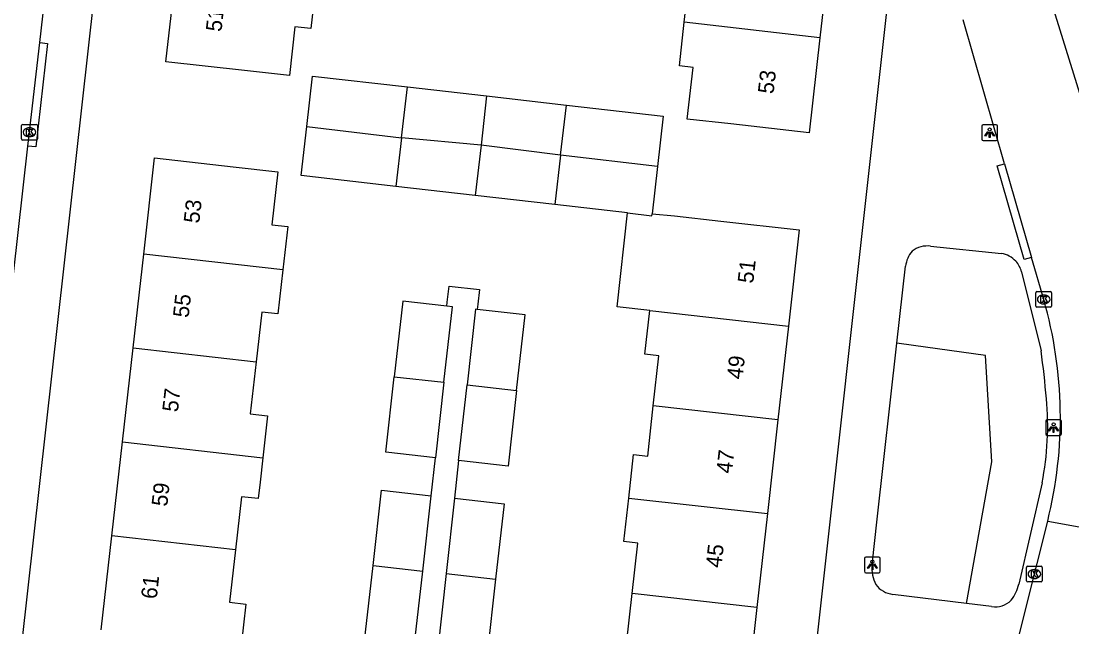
# Model space of a CAD drawing. Extents: x 162026 to 163499, y 387297 to 388169.
# Drawn here: x 162443.5 to 162510, y 387835.8 to 387874.2 of the extents above; entities that cross this region are included whole.
import ezdxf

# ---------------------------------------------------------------- set-up
doc = ezdxf.new("R2010")
doc.units = 0
for name, color, linetype in [('IMGEO_Groenvoorziening', 7, 'Continuous'), ('IMGEO_Kolk', 7, 'Continuous'), ('IMGEO_Lichtpunt', 7, 'Continuous'), ('IMGEO_Pand', 7, 'Continuous'), ('IMGEO_Pand_nummerreeks', 7, 'Continuous'), ('IMGEO_Rijbaan_lokaal_open', 7, 'Continuous'), ('IMGEO_Voetpad_open', 7, 'Continuous')]:
    doc.layers.add(name, color=color, linetype=linetype)

msp = doc.modelspace()

# ---------------------------------------------------------------- linework, layer by layer
at = {"layer": 'IMGEO_Groenvoorziening'}
msp.add_lwpolyline([(162503.359, 387837.251), (162504.95, 387846.219), (162504.552, 387852.97), (162500, 387853.601), (162498.938, 387853.747)], dxfattribs=at)
at = {"layer": 'IMGEO_Kolk'}
for p, q in [((162443.492, 387866.682), (162443.492, 387867.534)), ((162443.567, 387867.608), (162444.419, 387867.608)), ((162443.98, 387867.388), (162444.005, 387867.388)), ((162444.493, 387867.534), (162444.493, 387866.682)), ((162444.419, 387866.608), (162443.567, 387866.608)), ((162444.003, 387866.828), (162443.978, 387866.828)), ((162507.737, 387856.091), (162507.737, 387856.943)), ((162507.812, 387857.017), (162508.664, 387857.017)), ((162508.225, 387856.797), (162508.25, 387856.797)), ((162508.738, 387856.943), (162508.738, 387856.091)), ((162508.664, 387856.017), (162507.812, 387856.017)), ((162508.248, 387856.237), (162508.223, 387856.237)), ((162507.15, 387838.692), (162507.15, 387839.544)), ((162507.225, 387839.618), (162508.077, 387839.618)), ((162507.638, 387839.398), (162507.663, 387839.398)), ((162508.151, 387839.544), (162508.151, 387838.692)), ((162508.077, 387838.618), (162507.225, 387838.618)), ((162507.661, 387838.838), (162507.636, 387838.838))]:
    msp.add_line(p, q, dxfattribs=at)
for points in [[(162443.492, 387866.682), (162443.492, 387867.534)], [(162443.567, 387867.608), (162444.419, 387867.608)], [(162443.813, 387867.308), (162443.936, 387867.308), (162443.936, 387867.157), (162444.066, 387867.308), (162444.23, 387867.308), (162444.084, 387867.157), (162444.237, 387866.908), (162444.085, 387866.908), (162444, 387867.072), (162443.936, 387867.005), (162443.936, 387866.908), (162443.813, 387866.908), (162443.813, 387867.308)], [(162444.493, 387867.534), (162444.493, 387866.682)], [(162444.419, 387866.608), (162443.567, 387866.608)], [(162507.737, 387856.091), (162507.737, 387856.943)], [(162507.812, 387857.017), (162508.664, 387857.017)], [(162508.058, 387856.717), (162508.181, 387856.717), (162508.181, 387856.566), (162508.311, 387856.717), (162508.475, 387856.717), (162508.329, 387856.566), (162508.482, 387856.317), (162508.33, 387856.317), (162508.245, 387856.481), (162508.181, 387856.414), (162508.181, 387856.317), (162508.058, 387856.317), (162508.058, 387856.717)], [(162508.738, 387856.943), (162508.738, 387856.091)], [(162508.664, 387856.017), (162507.812, 387856.017)], [(162507.15, 387838.692), (162507.15, 387839.544)], [(162507.225, 387839.618), (162508.077, 387839.618)], [(162507.471, 387839.318), (162507.594, 387839.318), (162507.594, 387839.167), (162507.724, 387839.318), (162507.888, 387839.318), (162507.742, 387839.167), (162507.895, 387838.918), (162507.743, 387838.918), (162507.658, 387839.082), (162507.594, 387839.015), (162507.594, 387838.918), (162507.471, 387838.918), (162507.471, 387839.318)], [(162508.151, 387839.544), (162508.151, 387838.692)], [(162508.077, 387838.618), (162507.225, 387838.618)]]:
    msp.add_lwpolyline(points, dxfattribs=at)
for centre, start, end in [((162443.569, 387867.532), 91.55205, 178.44795), ((162443.569, 387867.532), 91.55205, 178.44795), ((162444.417, 387867.532), 1.55205, 88.44795), ((162444.417, 387867.532), 1.55205, 88.44795), ((162443.569, 387866.684), 181.55205, 268.44795), ((162443.569, 387866.684), 181.55205, 268.44795), ((162444.417, 387866.684), 271.55205, 358.44795), ((162444.417, 387866.684), 271.55205, 358.44795), ((162507.814, 387856.941), 91.55205, 178.44795), ((162507.814, 387856.941), 91.55205, 178.44795), ((162508.662, 387856.941), 1.55205, 88.44795), ((162508.662, 387856.941), 1.55205, 88.44795), ((162507.814, 387856.093), 181.55205, 268.44795), ((162507.814, 387856.093), 181.55205, 268.44795), ((162508.662, 387856.093), 271.55205, 358.44795), ((162508.662, 387856.093), 271.55205, 358.44795), ((162507.227, 387839.542), 91.55205, 178.44795), ((162507.227, 387839.542), 91.55205, 178.44795), ((162508.075, 387839.542), 1.55205, 88.44795), ((162508.075, 387839.542), 1.55205, 88.44795), ((162507.227, 387838.694), 181.55205, 268.44795), ((162507.227, 387838.694), 181.55205, 268.44795), ((162508.075, 387838.694), 271.55205, 358.44795), ((162508.075, 387838.694), 271.55205, 358.44795)]:
    msp.add_arc(centre, 0.0765, start, end, dxfattribs=at)
for centre, major_axis, ratio, start_param, end_param in [((162443.979, 387867.108), (-0.387, 0.002), 0.722429, 4.712389, 7.853982), ((162444.004, 387867.108), (-0.39, 0.002), 0.717154, 1.570796, 4.712389), ((162508.224, 387856.517), (-0.387, 0.002), 0.722429, 4.712389, 7.853982), ((162508.249, 387856.517), (-0.39, 0.002), 0.717154, 1.570796, 4.712389), ((162507.637, 387839.118), (-0.387, 0.002), 0.722429, 4.712389, 7.853982), ((162507.662, 387839.118), (-0.39, 0.002), 0.717154, 1.570796, 4.712389)]:
    msp.add_ellipse(centre, major_axis=major_axis, ratio=ratio, start_param=start_param, end_param=end_param, dxfattribs=at)
at = {"layer": 'IMGEO_Lichtpunt'}
for p, q in [((162504.317, 387867.483), (162504.317, 387866.676)), ((162504.317, 387867.483), (162504.317, 387866.676)), ((162505.219, 387867.578), (162504.411, 387867.578)), ((162505.219, 387867.578), (162504.411, 387867.578)), ((162505.313, 387866.676), (162505.313, 387867.483)), ((162505.313, 387866.676), (162505.313, 387867.483)), ((162504.411, 387866.582), (162505.219, 387866.582)), ((162504.411, 387866.582), (162505.219, 387866.582)), ((162508.366, 387848.802), (162508.366, 387847.995)), ((162508.366, 387848.802), (162508.366, 387847.995)), ((162509.268, 387848.897), (162508.46, 387848.897)), ((162509.268, 387848.897), (162508.46, 387848.897)), ((162509.362, 387847.995), (162509.362, 387848.802)), ((162509.362, 387847.995), (162509.362, 387848.802)), ((162508.46, 387847.901), (162509.268, 387847.901)), ((162508.46, 387847.901), (162509.268, 387847.901)), ((162496.888, 387840.099), (162496.888, 387839.292)), ((162496.888, 387840.099), (162496.888, 387839.292)), ((162497.79, 387840.194), (162496.982, 387840.194)), ((162497.79, 387840.194), (162496.982, 387840.194)), ((162497.884, 387839.292), (162497.884, 387840.099)), ((162497.884, 387839.292), (162497.884, 387840.099)), ((162496.982, 387839.198), (162497.79, 387839.198)), ((162496.982, 387839.198), (162497.79, 387839.198))]:
    msp.add_line(p, q, dxfattribs=at)
for points in [[(162504.691, 387867.147), (162504.73, 387867.119), (162504.542, 387866.857), (162504.504, 387866.884), (162504.691, 387867.147)], [(162504.793, 387867.099), (162504.84, 387867.099), (162504.84, 387866.777), (162504.793, 387866.777), (162504.793, 387867.099)], [(162504.903, 387867.119), (162504.941, 387867.146), (162505.128, 387866.884), (162505.089, 387866.856), (162504.903, 387867.119)], [(162508.74, 387848.466), (162508.779, 387848.438), (162508.591, 387848.176), (162508.553, 387848.203), (162508.74, 387848.466)], [(162508.952, 387848.438), (162508.99, 387848.465), (162509.177, 387848.203), (162509.138, 387848.175), (162508.952, 387848.438)], [(162508.842, 387848.418), (162508.889, 387848.418), (162508.889, 387848.096), (162508.842, 387848.096), (162508.842, 387848.418)], [(162497.262, 387839.763), (162497.301, 387839.735), (162497.113, 387839.473), (162497.075, 387839.5), (162497.262, 387839.763)], [(162497.364, 387839.715), (162497.411, 387839.715), (162497.411, 387839.393), (162497.364, 387839.393), (162497.364, 387839.715)], [(162497.474, 387839.735), (162497.512, 387839.762), (162497.699, 387839.5), (162497.66, 387839.472), (162497.474, 387839.735)]]:
    msp.add_lwpolyline(points, dxfattribs=at)
for centre in [(162504.816, 387867.281), (162508.865, 387848.6), (162497.387, 387839.897)]:
    msp.add_circle(centre, 0.0994, dxfattribs=at)
for centre, start, end in [((162504.411, 387867.483), 90, 180), ((162504.411, 387867.483), 90, 180), ((162505.219, 387867.483), 0, 90), ((162505.219, 387867.483), 0, 90), ((162504.411, 387866.676), 180, 270), ((162504.411, 387866.676), 180, 270), ((162505.219, 387866.676), 270, 0), ((162505.219, 387866.676), 270, 360), ((162508.46, 387848.802), 90, 180), ((162508.46, 387848.802), 90, 180), ((162509.268, 387848.802), 0, 90), ((162509.268, 387848.802), 0, 90), ((162508.46, 387847.995), 180, 270), ((162508.46, 387847.995), 180, 270), ((162509.268, 387847.995), 270, 0), ((162509.268, 387847.995), 270, 360), ((162496.982, 387840.099), 90, 180), ((162496.982, 387840.099), 90, 180), ((162497.79, 387840.099), 0, 90), ((162497.79, 387840.099), 0, 90), ((162496.982, 387839.292), 180, 270), ((162496.982, 387839.292), 180, 270), ((162497.79, 387839.292), 270, 0), ((162497.79, 387839.292), 270, 360)]:
    msp.add_arc(centre, 0.0946, start, end, dxfattribs=at)
at = {"layer": 'IMGEO_Pand'}
for points in [[(162485.472, 387874.075), (162485.783, 387876.833), (162486.69, 387876.73), (162487.057, 387879.847)], [(162494.736, 387878.97), (162494.065, 387873.095)], [(162462.123, 387876.468), (162461.81, 387873.681), (162460.811, 387873.793), (162460.463, 387870.694), (162457.603, 387871.014), (162452.634, 387871.571), (162453.303, 387877.469)], [(162494.065, 387873.095), (162493.378, 387867.075), (162488.41, 387867.634), (162485.657, 387867.944), (162486.042, 387871.216), (162485.161, 387871.315), (162485.472, 387874.075)], [(162494.065, 387873.095), (162485.472, 387874.075)], [(162461.553, 387867.47), (162461.919, 387870.668), (162467.948, 387869.977)], [(162467.567, 387866.759), (162467.948, 387869.977)], [(162467.948, 387869.977), (162472.949, 387869.404)], [(162472.949, 387869.404), (162472.595, 387866.295)], [(162472.949, 387869.404), (162478.005, 387868.824)], [(162477.631, 387865.657), (162478.005, 387868.824)], [(162478.005, 387868.824), (162484.138, 387868.121), (162483.772, 387864.931)], [(162467.203, 387863.678), (162461.197, 387864.367), (162461.553, 387867.47)], [(162461.553, 387867.47), (162467.567, 387866.759)], [(162467.567, 387866.759), (162467.203, 387863.678)], [(162472.595, 387866.295), (162467.567, 387866.759)], [(162472.595, 387866.295), (162472.231, 387863.102)], [(162477.631, 387865.657), (162472.595, 387866.295)], [(162451.226, 387859.39), (162451.917, 387865.488), (162456.886, 387864.925), (162459.715, 387864.604), (162459.335, 387861.248), (162460.35, 387861.133), (162460.039, 387858.391)], [(162477.631, 387865.657), (162477.261, 387862.525)], [(162483.772, 387864.931), (162477.631, 387865.657)], [(162483.772, 387864.931), (162483.429, 387861.94)], [(162472.231, 387863.102), (162467.203, 387863.678)], [(162477.261, 387862.525), (162472.231, 387863.102)], [(162481.88, 387861.996), (162477.261, 387862.525)], [(162483.281, 387855.81), (162481.212, 387856.042), (162481.88, 387861.996)], [(162481.88, 387861.996), (162483.415, 387861.82), (162483.429, 387861.94)], [(162483.429, 387861.94), (162484.858, 387861.802), (162487.788, 387861.474), (162492.756, 387860.917), (162492.073, 387854.825)], [(162450.552, 387853.44), (162451.226, 387859.39)], [(162460.039, 387858.391), (162451.226, 387859.39)], [(162460.039, 387858.391), (162459.722, 387855.598), (162458.709, 387855.712), (162458.351, 387852.556)], [(162470.428, 387856.084), (162467.639, 387856.397), (162467.102, 387851.617)], [(162470.242, 387851.265), (162470.779, 387856.045), (162470.428, 387856.084)], [(162472.349, 387855.879), (162472.244, 387855.891), (162471.711, 387851.1)], [(162474.852, 387850.751), (162475.385, 387855.541), (162472.349, 387855.879)], [(162483.509, 387849.771), (162483.866, 387852.951), (162482.97, 387853.052), (162483.281, 387855.81)], [(162483.281, 387855.81), (162492.073, 387854.825)], [(162492.073, 387854.825), (162491.407, 387848.885)], [(162449.877, 387847.49), (162450.552, 387853.44)], [(162450.552, 387853.44), (162458.351, 387852.556)], [(162458.351, 387852.556), (162457.978, 387849.262), (162459.074, 387849.138), (162458.773, 387846.482)], [(162469.705, 387846.481), (162466.564, 387846.834), (162467.102, 387851.617)], [(162467.102, 387851.617), (162470.242, 387851.265)], [(162470.242, 387851.265), (162469.705, 387846.481)], [(162471.178, 387846.31), (162471.711, 387851.1)], [(162471.711, 387851.1), (162474.852, 387850.751)], [(162474.852, 387850.751), (162474.319, 387845.96), (162471.178, 387846.31)], [(162481.949, 387843.93), (162482.26, 387846.69), (162483.152, 387846.589), (162483.509, 387849.771)], [(162491.407, 387848.885), (162483.509, 387849.771)], [(162491.407, 387848.885), (162490.741, 387842.945)], [(162449.203, 387841.54), (162449.877, 387847.49)], [(162449.877, 387847.49), (162458.773, 387846.482)], [(162458.773, 387846.482), (162458.599, 387844.945), (162458.481, 387843.899), (162457.419, 387844.019), (162457.037, 387840.652)], [(162465.758, 387839.658), (162466.294, 387844.428), (162469.434, 387844.075)], [(162468.899, 387839.305), (162469.434, 387844.075)], [(162470.913, 387843.925), (162470.381, 387839.145)], [(162470.913, 387843.925), (162474.054, 387843.576), (162473.522, 387838.795)], [(162482.177, 387837.891), (162482.534, 387841.071), (162481.638, 387841.172), (162481.949, 387843.93)], [(162481.949, 387843.93), (162490.741, 387842.945)], [(162490.741, 387842.945), (162490.075, 387837.005)], [(162448.529, 387835.59), (162449.203, 387841.54)], [(162457.037, 387840.652), (162449.203, 387841.54)], [(162457.037, 387840.652), (162456.661, 387837.333), (162457.7, 387837.215), (162457.402, 387834.584)], [(162468.363, 387834.533), (162465.222, 387834.885), (162465.758, 387839.658)], [(162465.758, 387839.658), (162468.899, 387839.305)], [(162468.363, 387834.533), (162468.899, 387839.305)], [(162470.381, 387839.145), (162469.85, 387834.369)], [(162470.381, 387839.145), (162473.522, 387838.795)], [(162473.522, 387838.795), (162472.991, 387834.02), (162469.85, 387834.369)], [(162480.617, 387832.05), (162480.928, 387834.81), (162481.82, 387834.709), (162482.177, 387837.891)], [(162490.075, 387837.005), (162482.177, 387837.891)], [(162490.075, 387837.005), (162489.409, 387831.065)]]:
    msp.add_lwpolyline(points, dxfattribs=at)
at = {"layer": 'IMGEO_Rijbaan_lokaal_open'}
for points in [[(162444.639, 387872.789), (162446.538, 387889.5), (162446.633, 387890.462), (162446.642, 387891.428), (162446.564, 387892.391), (162446.401, 387893.343), (162446.153, 387894.277), (162445.823, 387895.185), (162445.413, 387896.06), (162444.926, 387896.895), (162444.367, 387897.683), (162443.739, 387898.417), (162443.049, 387899.093), (162442.967, 387899.166), (162442.491, 387899.581), (162441.98, 387899.952), (162441.438, 387900.276), (162440.869, 387900.549), (162440.608, 387900.655), (162439.709, 387900.991), (162438.784, 387901.246), (162437.9, 387901.409), (162413.007, 387904.243)], [(162514.856, 387855.618), (162507.742, 387878.563)], [(162505.764, 387865.113), (162503.138, 387874.232)], [(162443.893, 387866.231), (162444.639, 387872.789)], [(162416.751, 387837.401), (162423.936, 387836.51), (162427.262, 387836.039), (162428.412, 387835.942), (162429.567, 387835.948), (162430.716, 387836.056), (162431.851, 387836.268), (162432.963, 387836.579), (162434.042, 387836.989), (162435.081, 387837.494), (162436.07, 387838.089), (162437.002, 387838.77), (162437.87, 387839.532), (162438.666, 387840.369), (162439.384, 387841.273), (162440.018, 387842.237), (162440.564, 387843.255), (162441.017, 387844.317), (162441.373, 387845.415), (162441.629, 387846.541), (162441.727, 387847.169), (162443.893, 387866.231)], [(162505.764, 387865.113), (162507.472, 387859.181)], [(162508.24, 387856.513), (162507.472, 387859.181)], [(162496.838, 387795.458), (162500, 387808.321), (162507.158, 387837.115), (162508.491, 387842.477)], [(162508.491, 387842.477), (162515.608, 387841.179)]]:
    msp.add_lwpolyline(points, dxfattribs=at)
msp.add_arc((162482.249, 387849.028), 27.047, 345.98323, 16.06574, dxfattribs=at)
at = {"layer": 'IMGEO_Voetpad_open'}
for points in [[(162489.932, 387799.465), (162494.267, 387838.446), (162500, 387890.005), (162501.72, 387906.704)], [(162451.123, 387903.043), (162443.098, 387831.258)], [(162444.639, 387872.789), (162445.136, 387872.739), (162444.39, 387866.181), (162443.893, 387866.231)], [(162507.472, 387859.181), (162506.994, 387859.037), (162505.286, 387864.969), (162505.764, 387865.113)], [(162501.078, 387859.896), (162505.574, 387859.433)], [(162498.938, 387853.747), (162499.487, 387858.632)], [(162506.835, 387858.266), (162508.073, 387853.269)], [(162470.428, 387856.084), (162470.458, 387856.347), (162470.572, 387857.355), (162472.491, 387857.138), (162472.387, 387856.216), (162472.349, 387855.879)], [(162497.381, 387839.696), (162497.686, 387842.604), (162498.938, 387853.747)], [(162469.434, 387844.075), (162469.705, 387846.481)], [(162471.178, 387846.31), (162470.913, 387843.925)], [(162508.135, 387844.902), (162506.665, 387838.483)], [(162503.359, 387837.251), (162498.684, 387837.834)], [(162504.943, 387837.054), (162503.359, 387837.251)]]:
    msp.add_lwpolyline(points, dxfattribs=at)
for centre, radius, start, end in [((162500.897, 387858.282), 1.624, 83.60463, 127.87462), ((162501.269, 387858.4), 1.797, 139.62369, 172.57688), ((162505.196, 387857.672), 1.801, 44.88278, 77.87842), ((162505.317, 387857.888), 1.564, 13.98584, 42.4136), ((162445, 387844.698), 63.653, 4.98362, 7.73812), ((162490.161, 387848.507), 18.332, 348.65891, 5.38666), ((162499.325, 387839.416), 1.964, 171.81663, 209.40043), ((162498.819, 387839.303), 1.475, 215.23226, 264.74885), ((162504.264, 387838.995), 2.455, 321.2643, 347.95679), ((162505.149, 387838.514), 1.475, 261.97787, 314.30695)]:
    msp.add_arc(centre, radius, start, end, dxfattribs=at)

# ---------------------------------------------------------------- texts
at = {"layer": 'IMGEO_Pand_nummerreeks'}
for s, rotation, p in [('51', 83.52586, (162456.147, 387873.441)), ('53', 83.48524, (162491.119, 387869.502)), ('53', 83.53458, (162454.745, 387861.308)), ('51', 83.606, (162489.837, 387857.504)), ('55', 83.53458, (162454.067, 387855.328)), ('49', 83.60314, (162489.155, 387851.422)), ('57', 83.53458, (162453.39, 387849.349)), ('47', 83.60314, (162488.486, 387845.452)), ('59', 83.53458, (162452.712, 387843.37)), ('45', 83.60314, (162487.817, 387839.482)), ('61', 83.53458, (162452.046, 387837.504))]:
    msp.add_text(s, height=1, rotation=rotation, dxfattribs=at).set_placement(p)

doc.saveas('drawing.dxf')
